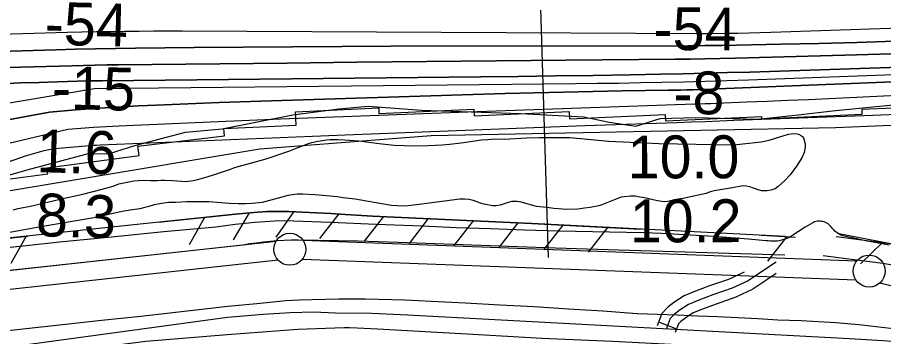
# Model space of a CAD drawing. Extents: x 3704301 to 3742427, y 506229 to 532009.
# Drawn here: x 3716465 to 3717817, y 518597 to 519096 of the extents above; entities that cross this region are included whole.
import ezdxf

# ---------------------------------------------------------------- set-up
doc = ezdxf.new("R2010")
doc.units = 0
for name, color, linetype in [('V-FLOD-BASE', 7, 'Continuous'), ('V-LEVE-TOET', 7, 'Continuous'), ('V-RIVR-EDGE', 7, 'Continuous'), ('V-RIVR-RANG', 7, 'Continuous'), ('V-ROAD-CNTR', 7, 'Continuous'), ('V-RRAP-FSHR', 7, 'Continuous'), ('V-RRAP-RVMT', 7, 'Continuous'), ('V-SITE-VEGE', 7, 'Continuous'), ('V-SURV-LINE', 7, 'Continuous'), ('V-TOPO-DPTH', 7, 'Continuous'), ('V-TOPO-MAJR', 7, 'Continuous'), ('V-TOPO-MINR', 7, 'Continuous'), ('V-TOPO-SHOR', 7, 'Continuous'), ('V-TOPO-WATR', 7, 'Continuous')]:
    doc.layers.add(name, color=color, linetype=linetype)

msp = doc.modelspace()

# ---------------------------------------------------------------- linework, layer by layer
at = {"layer": 'V-FLOD-BASE'}
for points in [[(3717662.5, 518724.4), (3717610.6, 518726.1), (3717558.6, 518727.7), (3717506.6, 518729.2), (3717454.6, 518730.7), (3717402.7, 518732), (3717288.3, 518736), (3717173.9, 518739.9), (3717059.5, 518743.9), (3717028.2, 518745.1), (3716996.8, 518746), (3716965.5, 518746.8), (3716934.1, 518747.4), (3716902.8, 518747.9), (3716892, 518747.6), (3716881.2, 518747.2), (3716870.4, 518746.5), (3716859.7, 518745.6), (3716848.9, 518744.6), (3716838.2, 518743.3), (3716827.5, 518741.9), (3716816.9, 518740.2), (3716711.8, 518728.5), (3716606.7, 518717), (3716501.6, 518705.6), (3716402.9, 518695.2)], [(3717836, 518707.9), (3717815.5, 518711.1), (3717795, 518714), (3717774.4, 518716.6), (3717722.4, 518723.1)]]:
    msp.add_lwpolyline(points, dxfattribs=at)
at = {"layer": 'V-LEVE-TOET'}
for points in [[(3717825.3, 518739.8), (3717805.9, 518743.4), (3717788.1, 518747), (3717770.3, 518750.7), (3717752.6, 518754.6), (3717749.9, 518755.8), (3717747.3, 518757.1), (3717744.9, 518758.6), (3717742.5, 518760.3), (3717740.3, 518762.1), (3717738.2, 518764.2), (3717736.3, 518766.3), (3717734.6, 518768.6), (3717733.1, 518770.3), (3717731.5, 518771.8), (3717729.8, 518773.1), (3717728, 518774.3), (3717726, 518775.3), (3717724, 518776.2), (3717721.9, 518776.8), (3717719.7, 518777.2), (3717717.6, 518777.5), (3717715.4, 518777.5), (3717713.2, 518777.3), (3717711, 518776.9), (3717708.9, 518776.4), (3717706.9, 518775.6), (3717704.9, 518774.6), (3717694.1, 518768.1), (3717683.5, 518761.4), (3717673.1, 518754.3), (3717670.1, 518752.6), (3717667, 518751.1), (3717663.7, 518749.8), (3717660.4, 518748.6), (3717657.1, 518747.7), (3717653.7, 518747), (3717650.2, 518746.4), (3717646.8, 518746.1), (3717643.3, 518746), (3717639.8, 518746.2), (3717636.3, 518746.5), (3717632.9, 518747), (3717605.7, 518749.4), (3717578.6, 518751.6), (3717551.4, 518753.5), (3717524.2, 518755.3), (3717497, 518756.7), (3717469.8, 518758), (3717442.6, 518759), (3717415.3, 518759.8), (3717362.2, 518760.8), (3717309, 518762.1), (3717255.9, 518763.6), (3717202.8, 518765.4), (3717149.6, 518767.3), (3717096.5, 518769.5), (3717024.9, 518772.5), (3716953.2, 518775.4), (3716881.5, 518778), (3716866.2, 518777.4), (3716850.8, 518776.5), (3716835.5, 518775.3), (3716820.2, 518773.9), (3716804.9, 518772.3), (3716789.7, 518770.4), (3716774.5, 518768.3), (3716693.1, 518760.6), (3716611.7, 518752.6), (3716530.4, 518744.6)], [(3716530.4, 518744.6), (3716473.8, 518738.5), (3716417.1, 518732.6)], [(3716413, 518602.4), (3716474.1, 518609.4), (3716535.2, 518616.2), (3716596.3, 518622.7), (3716657.4, 518629), (3716702.6, 518634.4), (3716747.8, 518639.6), (3716793.1, 518644.4), (3716838.3, 518649), (3716883.6, 518653.3), (3716904.3, 518654.4), (3716924.9, 518655.2), (3716945.5, 518655.7), (3716966.2, 518656.1), (3716986.8, 518656.2), (3717007.5, 518656.1), (3717028.1, 518655.8), (3717048.7, 518655.2), (3717069.4, 518654.5), (3717090, 518653.5), (3717110.6, 518652.2), (3717164.2, 518649.7), (3717217.7, 518646.9), (3717271.3, 518643.9), (3717324.9, 518640.7), (3717378.4, 518637.2), (3717431.9, 518633.4), (3717463.3, 518632.3), (3717494.7, 518631.1), (3717526.1, 518629.7), (3717557.5, 518628.3), (3717588.8, 518626.8), (3717620.2, 518625.1), (3717651.6, 518623.4), (3717669.7, 518622.9), (3717687.7, 518622.2), (3717705.8, 518621.3), (3717723.9, 518620.3), (3717741.9, 518619), (3717760, 518617.5), (3717778, 518615.8), (3717796, 518614), (3717813.9, 518611.9), (3717831.9, 518609.6)]]:
    msp.add_lwpolyline(points, dxfattribs=at)
at = {"layer": 'V-RIVR-EDGE'}
for points in [[(3716966.3, 518953.1), (3717012, 518957.1), (3717095.4, 518950.9), (3717250.3, 518945.8), (3717348.7, 518940.7), (3717388.3, 518932.2), (3717429.7, 518926.1), (3717467.6, 518938), (3717522.8, 518939.7), (3717620, 518937), (3717683.1, 518943.5), (3717736.5, 518950), (3717831.4, 518959.3), (3717916.1, 518958.5), (3718003.7, 518951.7), (3718088.4, 518958.7), (3718198.2, 518966.2), (3718336.3, 518972.5), (3718470.8, 518979.4), (3718576.5, 518990.5), (3718613.1, 518992.2), (3718677.3, 518988.4)], [(3716419.2, 518840.3), (3716485.8, 518859.4), (3716573.5, 518882.6), (3716608.4, 518883.1), (3716648, 518895.6), (3716727.3, 518916.4), (3716784.4, 518921.7), (3716894.9, 518943.6), (3716966.3, 518953.1)]]:
    msp.add_lwpolyline(points, dxfattribs=at)
at = {"layer": 'V-RIVR-RANG'}
msp.add_line((3717293.8, 518720.7), (3717262.8, 519720.2), dxfattribs=at)
at = {"layer": 'V-ROAD-CNTR'}
msp.add_line((3717465.4, 518620.1), (3717493.4, 518609.4), dxfattribs=at)
for points in [[(3717648.6, 518713.4), (3717627.7, 518699.4), (3717605.2, 518684.4), (3717580, 518672.6), (3717550, 518662.1), (3717528.3, 518654.1), (3717512.2, 518647.3), (3717499.3, 518638.9), (3717490.2, 518632.1), (3717483.4, 518625.1), (3717477.1, 518608.7)], [(3717598.7, 518697.9), (3717574.3, 518686.5), (3717544.9, 518676.3), (3717522.8, 518668.1), (3717505.1, 518660.6), (3717490.7, 518651.2), (3717480.3, 518643.4), (3717470.5, 518633.4), (3717463.1, 518614.1)], [(3717648.8, 518695.5), (3717636, 518686.9), (3717612.6, 518671.3), (3717585.7, 518658.7), (3717555, 518648), (3717533.8, 518640.1), (3717519.3, 518634.1), (3717508, 518626.6), (3717500.1, 518620.7), (3717496.3, 518616.8), (3717491.1, 518603.4)], [(3718781, 518498.2), (3718179.1, 518515), (3718151.7, 518517.6), (3718130.4, 518521.2), (3718088, 518530), (3717980.9, 518561), (3717958.8, 518565.9), (3717941.7, 518570.4), (3717923.5, 518575.1), (3717898.8, 518579.2), (3717869, 518585), (3717837.9, 518589.1), (3717807.1, 518590.8), (3717763.1, 518593.4), (3717074.3, 518630.3), (3717017.9, 518633), (3716960.9, 518633.9), (3716927.6, 518635.5), (3716890.7, 518634.2), (3716848.3, 518631.5), (3716792.9, 518627.1), (3716349.3, 518566.6)]]:
    msp.add_lwpolyline(points, dxfattribs=at)
at = {"layer": 'V-RRAP-FSHR'}
for p, q in [((3716756.7, 518783.4), (3716733.1, 518740.7)), ((3716826.4, 518790.3), (3716801.6, 518748.2)), ((3716896.3, 518792.6), (3716868.2, 518752.7)), ((3716966.2, 518789), (3716936.3, 518750.3)), ((3717036.1, 518784.6), (3717006.2, 518746)), ((3717106, 518781.4), (3717076.2, 518742.7)), ((3716687.1, 518776), (3716686.9, 518775.7)), ((3717175.9, 518778.1), (3717146.1, 518739.4)), ((3717245.8, 518774.8), (3717216, 518736.2)), ((3717315.8, 518771.3), (3717285.7, 518732.8)), ((3717385.7, 518767.7), (3717355.6, 518729.2)), ((3716478.3, 518753.9), (3716454.7, 518711.2)), ((3717665.3, 518753.3), (3717635.3, 518714.8)), ((3717815.5, 518744.6), (3717780.5, 518710.6))]:
    msp.add_line(p, q, dxfattribs=at)
for points in [[(3713987.6, 518174.3), (3714448.8, 518564.7), (3714742.2, 518696.9), (3715881.9, 518753.3), (3716266.3, 518793.9), (3716843.1, 518890.7), (3717110.3, 518911.2), (3717741.3, 518924), (3718486.4, 518954.9), (3719294.8, 519011.2), (3719786.3, 519085.8), (3720431.3, 519110.6), (3720895.9, 519113.1), (3721218.5, 519068.4), (3721397.7, 519012.5), (3721721.3, 518965.4), (3721950.6, 518904.5), (3722606.9, 518712.5), (3722865.7, 518669.5), (3723100.5, 518674.8), (3723533.4, 518647.1), (3724154, 518573), (3724673.7, 518469.2)], [(3717663.1, 518753.5), (3717267.4, 518773.8), (3717018.9, 518785.4), (3716993.5, 518786.9), (3716976.5, 518787.7), (3716954, 518789.5), (3716920.4, 518791.1), (3716888.6, 518792.6), (3716854.4, 518792.7), (3716833.8, 518790.8), (3716805.2, 518788.6), (3716557.6, 518762.3), (3716144.9, 518718.6)], [(3716684.9, 518775.8), (3716805.2, 518788.6), (3716833.8, 518790.8), (3716854.4, 518792.7), (3716888.6, 518792.6), (3716920.4, 518791.1), (3716954, 518789.5), (3716976.5, 518787.7), (3716993.5, 518786.9), (3717018.9, 518785.4), (3717267.4, 518773.8), (3717437.1, 518765.1)], [(3715731, 518676.1), (3715900.5, 518692.4), (3716036.8, 518707.7), (3716045, 518711.2), (3716062.2, 518722.3), (3716074, 518726.7), (3716089.3, 518730.4), (3716103, 518730.2), (3716113, 518728.5), (3716130.4, 518723.7), (3716144.9, 518718.6), (3716480.7, 518754.1)], [(3717626.2, 518755.4), (3717679, 518752.6)], [(3718861.5, 518635.8), (3718367.7, 518650.2), (3718265.8, 518650.6), (3718237.8, 518650.1), (3718217.4, 518650.6), (3718200.3, 518651.7), (3718184.6, 518653.5), (3718163.8, 518658.1), (3718142.7, 518661.9), (3718022.9, 518693.8), (3717983.3, 518705.8), (3717948.3, 518717.1), (3717925.8, 518722.8), (3717893.1, 518732.7), (3717875.8, 518735), (3717849.6, 518738.6), (3717822.3, 518743.3), (3717746.8, 518757.8)], [(3717742.6, 518753.4), (3717822.3, 518743.3), (3717849.6, 518738.6), (3717875.8, 518735), (3717893.1, 518732.7), (3717925.8, 518722.8), (3717948.3, 518717.1), (3717983.3, 518705.8), (3718022.9, 518693.8), (3718142.7, 518661.9), (3718163.8, 518658.1), (3718184.6, 518653.5), (3718200.3, 518651.7), (3718210.7, 518651)]]:
    msp.add_lwpolyline(points, dxfattribs=at)
at = {"layer": 'V-RRAP-RVMT'}
msp.add_lwpolyline([(3716371.4, 518832.5), (3716512.1, 518851.4), (3716510.8, 518860.9), (3716654.8, 518880.2), (3716652.9, 518894.9), (3716788.2, 518910.7), (3716786.9, 518922.3), (3716899.8, 518927.5), (3716898.8, 518948.6), (3717028.7, 518954.6), (3717029.1, 518945.6), (3717177.3, 518952.5), (3717177.7, 518942.2), (3717325.9, 518949), (3717326.4, 518937.5), (3717475.8, 518944.4), (3717476.2, 518934.1), (3717625.9, 518941), (3717626, 518937.5), (3717783.1, 518944.8), (3717782.8, 518952.3), (3717904.6, 518957.9)], dxfattribs=at)
at = {"layer": 'V-SITE-VEGE'}
for points in [[(3716739.3, 518841.3), (3716746.2, 518842.7), (3716753.6, 518844.7), (3716762.3, 518847.5), (3716771, 518849.9), (3716778.7, 518852.4), (3716797.2, 518858.9), (3716802.8, 518860.6), (3716809.3, 518862.9), (3716828.6, 518867.9), (3716853.2, 518874.7), (3716888.4, 518887.1), (3716903.9, 518893.2), (3716911.2, 518895.9), (3716917.7, 518898.5), (3716924.3, 518900.5), (3716931.1, 518902.2), (3716947.1, 518904.8), (3716952.7, 518904.9), (3716965.6, 518905.3), (3716975.4, 518904.8), (3716997.8, 518902.9), (3717017.4, 518900.6), (3717029.4, 518898.9), (3717052.9, 518896.4), (3717084.2, 518895.4), (3717105.9, 518895.9), (3717117.1, 518896.5), (3717127.5, 518896.7), (3717139.1, 518897.7), (3717157.3, 518900), (3717164.5, 518901), (3717171.7, 518902.2), (3717188.3, 518904.5), (3717198.7, 518905.3), (3717209.3, 518906.2), (3717224.6, 518905.9), (3717259.1, 518907.9), (3717279, 518908.2), (3717300.6, 518908.5), (3717327, 518908), (3717387.8, 518902.6), (3717466, 518898.9), (3717582.7, 518896.9), (3717625.2, 518901.7), (3717638, 518904.1), (3717663.1, 518912.1), (3717668.5, 518913.5), (3717675.9, 518914.3), (3717681.8, 518914), (3717683.3, 518913.7), (3717685.2, 518912.9), (3717686.5, 518912.1), (3717688.4, 518910.9), (3717689.7, 518909.7), (3717691.3, 518907.6), (3717692.6, 518904.2), (3717693.7, 518900.5), (3717694.1, 518896.8), (3717694.3, 518893.3), (3717692.3, 518884.6), (3717689.1, 518876.4), (3717680.6, 518863.2), (3717670.7, 518849.7), (3717661.9, 518840.4), (3717652.2, 518831.9), (3717647.3, 518828.2), (3717640.7, 518825.7), (3717634.8, 518824.8), (3717626.5, 518824.9), (3717620.6, 518826.6), (3717613.6, 518829.3), (3717607.8, 518831.3), (3717602.1, 518832.3), (3717596.7, 518832.6), (3717580.9, 518829.7), (3717551.9, 518825.1), (3717546.1, 518823.2), (3717539.4, 518820.6), (3717510.6, 518814.6), (3717503.8, 518813.1), (3717495.7, 518812), (3717489.5, 518810.7), (3717483.8, 518809.2), (3717479.7, 518808.4), (3717474.5, 518807.8), (3717470.2, 518808.1), (3717463.7, 518809.2), (3717443.3, 518813.7), (3717436.1, 518815.2), (3717428.8, 518816.3), (3717421.5, 518816.4), (3717411.6, 518815.7), (3717407, 518815), (3717402.6, 518813.5), (3717384.8, 518805.9), (3717377, 518803), (3717371.9, 518801.6), (3717358.4, 518798.9), (3717349.7, 518797.7), (3717339.2, 518796.4)], [(3716458, 518795.4), (3716466, 518797.2), (3716487.4, 518801.3), (3716540.5, 518814.1), (3716567.2, 518819.9), (3716597.2, 518827.4), (3716614.5, 518832.4), (3716623.3, 518835.6), (3716630.8, 518837.4), (3716638.7, 518839), (3716646.5, 518840.3), (3716653.3, 518841.1), (3716662.2, 518841.8), (3716672.6, 518841.2), (3716678, 518841.3), (3716683.1, 518841.1), (3716688.6, 518841.4), (3716694.8, 518841.5), (3716706.7, 518841), (3716727.7, 518839.6), (3716739.3, 518841.3)], [(3716887, 518817.7), (3716883.4, 518816.6), (3716872, 518813.6), (3716846.9, 518806.4), (3716831.2, 518805.1), (3716820.8, 518804.4), (3716809.2, 518804.6), (3716795.3, 518805.2), (3716763.5, 518807.9), (3716729.5, 518807.7), (3716711.9, 518806.9), (3716701.4, 518806.7), (3716693.3, 518805.8), (3716684.2, 518804.3), (3716678.1, 518802.8), (3716670.1, 518800.6), (3716663.9, 518798.7), (3716656.1, 518796.9), (3716640.8, 518794.9), (3716628.4, 518792.7), (3716584, 518782.7), (3716501.3, 518768.5), (3716449.9, 518759)], [(3717339.2, 518796.4), (3717321.8, 518795.8), (3717309, 518797), (3717301.7, 518797.5), (3717294.6, 518798.4), (3717285.2, 518799.2), (3717275, 518800.5), (3717251, 518807.1), (3717244.9, 518808.2), (3717236.1, 518808), (3717229.3, 518806.2), (3717218.1, 518802.6), (3717211.5, 518801.7), (3717206.2, 518801.6), (3717193, 518804), (3717187.7, 518805.8), (3717176.7, 518809.8), (3717169.4, 518811.6), (3717162.8, 518812.1), (3717155.3, 518811.9), (3717119.4, 518807.2), (3717091.9, 518803.3), (3717070.6, 518801.1), (3717057.9, 518801.5), (3717048.7, 518802.2), (3717030.3, 518804.9), (3716991.8, 518812), (3716973.2, 518814.2), (3716963.7, 518815.7), (3716952.8, 518816.6), (3716941.6, 518817.8), (3716929, 518818.8), (3716909.8, 518819.5), (3716901.4, 518819.6), (3716887, 518817.7)]]:
    msp.add_lwpolyline(points, dxfattribs=at)
at = {"layer": 'V-SURV-LINE'}
for points in [[(3715037.6, 518545.5), (3716868.4, 518746.2)], [(3716910.4, 518747.7), (3717774.6, 518715.3)], [(3716871.7, 518716.4), (3715040.9, 518515.7)], [(3717773.5, 518685.3), (3716909.3, 518717.8)], [(3718159.7, 518598.3), (3717810.1, 518680.4)]]:
    msp.add_lwpolyline(points, dxfattribs=at)
for centre in [(3716889.9, 518733.5), (3717794, 518699.5)]:
    msp.add_circle(centre, 25, dxfattribs=at)
at = {"layer": 'V-TOPO-DPTH'}
for points in [[(3717833.7, 519059), (3717774.6, 519057), (3717715.4, 519055.4), (3717656.2, 519054.1), (3717564.1, 519052.3), (3717551, 519052.1), (3717537.9, 519051.9), (3717524.7, 519051.8), (3717511.6, 519051.7), (3717047.8, 519050.8), (3716971, 519050.6), (3716894.2, 519050.2), (3716817.3, 519049.6), (3716740.5, 519048.9), (3716649.1, 519048), (3716618, 519047.6), (3716586.8, 519047), (3716555.7, 519046.3), (3716524.6, 519045.5), (3716155.7, 519034.6)], [(3717833.7, 519059), (3717774.6, 519057), (3717715.4, 519055.4), (3717656.2, 519054.1), (3717564.1, 519052.3), (3717551, 519052.1), (3717537.9, 519051.9), (3717524.7, 519051.8), (3717511.6, 519051.7), (3717047.8, 519050.8), (3716971, 519050.6), (3716894.2, 519050.2), (3716817.3, 519049.6), (3716740.5, 519048.9), (3716649.1, 519048), (3716618, 519047.6), (3716586.8, 519047), (3716555.7, 519046.3), (3716524.6, 519045.5), (3716155.7, 519034.6)], [(3717847.7, 519039.3), (3717756.2, 519036.7), (3717584.9, 519032.3), (3717561.4, 519031.7), (3717538, 519031.2), (3717514.5, 519030.9), (3717491, 519030.6), (3717320.5, 519029), (3717211.8, 519028), (3717103.1, 519026.9), (3716994.4, 519025.8), (3716885.6, 519024.7), (3716622.6, 519021.9), (3716604.4, 519021.7), (3716586.1, 519021.4), (3716567.9, 519021), (3716549.6, 519020.5), (3716409.6, 519016.5)], [(3716409.6, 519016.5), (3716549.6, 519020.5), (3716567.9, 519021), (3716586.1, 519021.4), (3716604.4, 519021.7), (3716622.6, 519021.9), (3716885.6, 519024.7), (3716994.4, 519025.8), (3717103.1, 519026.9), (3717211.8, 519028), (3717320.5, 519029), (3717491, 519030.6), (3717514.5, 519030.9), (3717538, 519031.2), (3717561.4, 519031.7), (3717584.9, 519032.3), (3717756.2, 519036.7), (3717847.7, 519039.3)], [(3715672.4, 518792), (3716515.1, 518948), (3716549.7, 518951), (3716584.4, 518953.7), (3716619, 518955.8), (3716653.7, 518957.6), (3716682, 518958.9), (3716730.9, 518961), (3716779.7, 518962.9), (3716828.6, 518964.6), (3716877.5, 518966.2), (3717225.8, 518976.9), (3717271.4, 518978.2), (3717317.1, 518979.3), (3717362.7, 518980.2), (3717408.3, 518981), (3717480.3, 518982.1), (3717490, 518982.2), (3717499.6, 518982.4), (3717509.2, 518982.6), (3717518.9, 518982.9), (3717528.5, 518983.1), (3717538.2, 518983.4), (3717547.8, 518983.8), (3717557.5, 518984.1), (3718234.4, 519011.4)], [(3718234.4, 519011.4), (3717557.5, 518984.1), (3717547.8, 518983.8), (3717538.2, 518983.4), (3717528.5, 518983.1), (3717518.9, 518982.9), (3717509.2, 518982.6), (3717499.6, 518982.4), (3717490, 518982.2), (3717480.3, 518982.1), (3717408.3, 518981), (3717362.7, 518980.2), (3717317.1, 518979.3), (3717271.4, 518978.2), (3717225.8, 518976.9), (3716877.5, 518966.2), (3716828.6, 518964.6), (3716779.7, 518962.9), (3716730.9, 518961), (3716682, 518958.9), (3716653.7, 518957.6), (3716619, 518955.8), (3716584.4, 518953.7), (3716549.7, 518951), (3716515.1, 518948), (3715672.4, 518792)], [(3717997.8, 519023.4), (3717607.7, 519010.6), (3717572.9, 519009.6), (3717538.1, 519008.6), (3717503.2, 519007.8), (3717468.4, 519007.1), (3717421.4, 519006.3), (3717363.1, 519005.4), (3717304.7, 519004.5), (3717246.4, 519003.8), (3717188.1, 519003.1), (3716597.3, 518997), (3716591.4, 518997), (3716585.5, 518996.9), (3716579.5, 518996.7), (3716573.6, 518996.6), (3716527.5, 518995.3), (3716498.6, 518994.4), (3716469.6, 518993.5), (3716440.7, 518992.3)], [(3716440.7, 518992.3), (3716469.6, 518993.5), (3716498.6, 518994.4), (3716527.5, 518995.3), (3716573.6, 518996.6), (3716579.5, 518996.7), (3716585.5, 518996.9), (3716591.4, 518997), (3716597.3, 518997), (3717188.1, 519003.1), (3717246.4, 519003.8), (3717304.7, 519004.5), (3717363.1, 519005.4), (3717421.4, 519006.3), (3717468.4, 519007.1), (3717503.2, 519007.8), (3717538.1, 519008.6), (3717572.9, 519009.6), (3717607.7, 519010.6), (3717997.8, 519023.4)], [(3716327.1, 518827.2), (3716470.2, 518877), (3716477.4, 518879.4), (3716484.7, 518881.7), (3716492, 518884), (3716499.3, 518886.1), (3716506.7, 518887.9), (3716514.1, 518889.5), (3716521.6, 518890.7), (3716529.1, 518891.6), (3716571.6, 518895.3), (3716577.2, 518895.7), (3716582.7, 518896.1), (3716588.3, 518896.4), (3716593.8, 518896.7), (3716976.2, 518912.4), (3717069.9, 518916.2), (3717163.6, 518919.9), (3717257.3, 518923.4), (3717351, 518926.8), (3717493.9, 518931.9), (3717516.1, 518932.7), (3717538.4, 518933.5), (3717560.7, 518934.3), (3717583, 518935.1), (3717712.9, 518939.8), (3717800.1, 518943.2), (3717887.3, 518946.8)]]:
    msp.add_lwpolyline(points, dxfattribs=at)
at = {"layer": 'V-TOPO-MAJR'}
msp.add_lwpolyline([(3715773.6, 519049.8), (3716542.8, 519072.7), (3716565.2, 519073.3), (3716587.6, 519073.9), (3716610, 519074.2), (3716632.4, 519074.5), (3716654.8, 519074.7), (3716677.1, 519074.8), (3716699.5, 519074.8), (3716721.9, 519074.8), (3717530.6, 519070.9), (3717534.2, 519070.9), (3717537.8, 519070.9), (3717541.4, 519070.9), (3717545, 519070.9), (3717572, 519071.3), (3717589.1, 519071.6), (3717606.2, 519071.9), (3717623.3, 519072.4), (3717640.4, 519072.9), (3718292.2, 519094.8)], dxfattribs=at)
at = {"layer": 'V-TOPO-MINR'}
for points in [[(3715824.5, 518856.7), (3716585.1, 518985.1), (3717335.6, 518992.6), (3717369.3, 518993), (3717403.1, 518993.4), (3717436.9, 518994), (3717470.6, 518994.7), (3717504.4, 518995.5), (3717538.1, 518996.4), (3717571.9, 518997.5), (3717605.6, 518998.6), (3718116.7, 519017.2), (3718148, 519018.4), (3718179.4, 519019.8), (3718210.7, 519021.3), (3718242, 519022.9), (3718273.3, 519024.7), (3718304.6, 519026.7), (3718335.8, 519028.7), (3718367.1, 519031), (3719045.6, 519080.6)], [(3716155.7, 519034.6), (3716524.6, 519045.5), (3716555.7, 519046.3), (3716586.8, 519047), (3716618, 519047.6), (3716649.1, 519048), (3716740.5, 519048.9), (3716817.3, 519049.6), (3716894.2, 519050.2), (3716971, 519050.6), (3717047.8, 519050.8), (3717511.6, 519051.7), (3717524.7, 519051.8), (3717537.9, 519051.9), (3717551, 519052.1), (3717564.1, 519052.3), (3717656.2, 519054.1), (3717715.4, 519055.4), (3717774.6, 519057), (3717833.7, 519059)], [(3716409.6, 519016.5), (3716549.6, 519020.5), (3716567.9, 519021), (3716586.1, 519021.4), (3716604.4, 519021.7), (3716622.6, 519021.9), (3716885.6, 519024.7), (3716994.4, 519025.8), (3717103.1, 519026.9), (3717211.8, 519028), (3717320.5, 519029), (3717491, 519030.6), (3717514.5, 519030.9), (3717538, 519031.2), (3717561.4, 519031.7), (3717584.9, 519032.3), (3717756.2, 519036.7), (3717847.7, 519039.3)], [(3715672.4, 518792), (3716515.1, 518948), (3716549.7, 518951), (3716584.4, 518953.7), (3716619, 518955.8), (3716653.7, 518957.6), (3716682, 518958.9), (3716730.9, 518961), (3716779.7, 518962.9), (3716828.6, 518964.6), (3716877.5, 518966.2), (3717225.8, 518976.9), (3717271.4, 518978.2), (3717317.1, 518979.3), (3717362.7, 518980.2), (3717408.3, 518981), (3717480.3, 518982.1), (3717490, 518982.2), (3717499.6, 518982.4), (3717509.2, 518982.6), (3717518.9, 518982.9), (3717528.5, 518983.1), (3717538.2, 518983.4), (3717547.8, 518983.8), (3717557.5, 518984.1), (3718234.4, 519011.4)], [(3716440.7, 518992.3), (3716469.6, 518993.5), (3716498.6, 518994.4), (3716527.5, 518995.3), (3716573.6, 518996.6), (3716579.5, 518996.7), (3716585.5, 518996.9), (3716591.4, 518997), (3716597.3, 518997), (3717188.1, 519003.1), (3717246.4, 519003.8), (3717304.7, 519004.5), (3717363.1, 519005.4), (3717421.4, 519006.3), (3717468.4, 519007.1), (3717503.2, 519007.8), (3717538.1, 519008.6), (3717572.9, 519009.6), (3717607.7, 519010.6), (3717997.8, 519023.4)], [(3715999.7, 518792.2), (3716543.8, 518921.3), (3716563.7, 518923), (3716583.5, 518924.4), (3716603.4, 518925.6), (3716623.3, 518926.6), (3716778.2, 518933.2), (3716875.6, 518937.3), (3716973, 518941.2), (3717070.4, 518944.8), (3717167.7, 518948.3), (3717521.6, 518960.7), (3717529.9, 518961), (3717538.3, 518961.3), (3717546.7, 518961.6), (3717555, 518961.9), (3717602.7, 518963.8), (3717634.9, 518965.1), (3717667, 518966.4), (3717699.2, 518967.9), (3717731.4, 518969.4), (3718293.6, 518996.8)]]:
    msp.add_lwpolyline(points, dxfattribs=at)
at = {"layer": 'V-TOPO-SHOR'}
msp.add_lwpolyline([(3717785.5, 518571.4), (3717752.4, 518571.7), (3717722.1, 518571.6), (3717717.7, 518572.5), (3717713.9, 518573.3), (3717709.4, 518573.9), (3717705.1, 518574.5), (3717701.3, 518574.9), (3717693.7, 518574.8), (3717643.3, 518578), (3717545.7, 518582.5), (3717485.2, 518584.9), (3717393.5, 518589.4), (3717283.4, 518594.3), (3717166.7, 518600.9), (3717026.9, 518608.5), (3716994.9, 518610.1), (3716983, 518611), (3716974.9, 518611), (3716902.2, 518608.1), (3716792.4, 518600), (3716665.2, 518589.2), (3716506.8, 518568.9), (3716459.1, 518562.6)], dxfattribs=at)
at = {"layer": 'V-TOPO-WATR'}
msp.add_lwpolyline([(3716327.1, 518827.2), (3716470.2, 518877), (3716477.4, 518879.4), (3716484.7, 518881.7), (3716492, 518884), (3716499.3, 518886.1), (3716506.7, 518887.9), (3716514.1, 518889.5), (3716521.6, 518890.7), (3716529.1, 518891.6), (3716571.6, 518895.3), (3716577.2, 518895.7), (3716582.7, 518896.1), (3716588.3, 518896.4), (3716593.8, 518896.7), (3716976.2, 518912.4), (3717069.9, 518916.2), (3717163.6, 518919.9), (3717257.3, 518923.4), (3717351, 518926.8), (3717493.9, 518931.9), (3717516.1, 518932.7), (3717538.4, 518933.5), (3717560.7, 518934.3), (3717583, 518935.1), (3717712.9, 518939.8), (3717800.1, 518943.2), (3717887.3, 518946.8)], dxfattribs=at)

# ---------------------------------------------------------------- texts
at = {"layer": 'V-RIVR-RANG'}
for s, rotation, p in [('-54', 358.5781, (3716506.9, 519053.5)), ('-54', 359.5836, (3717457.3, 519045.1)), ('-15', 358.5781, (3716518.1, 518953.2)), ('-8', 0.1283, (3717488.4, 518944.4)), ('1.6', 358.2983, (3716494.1, 518854.2)), ('10.0', 0.1283, (3717417.2, 518844.3)), ('8.3', 358.2983, (3716493.3, 518754.2)), ('10.2', 0.1283, (3717420.5, 518744.3))]:
    msp.add_text(s, height=67, rotation=rotation, dxfattribs=at).set_placement(p)

doc.saveas('drawing.dxf')
